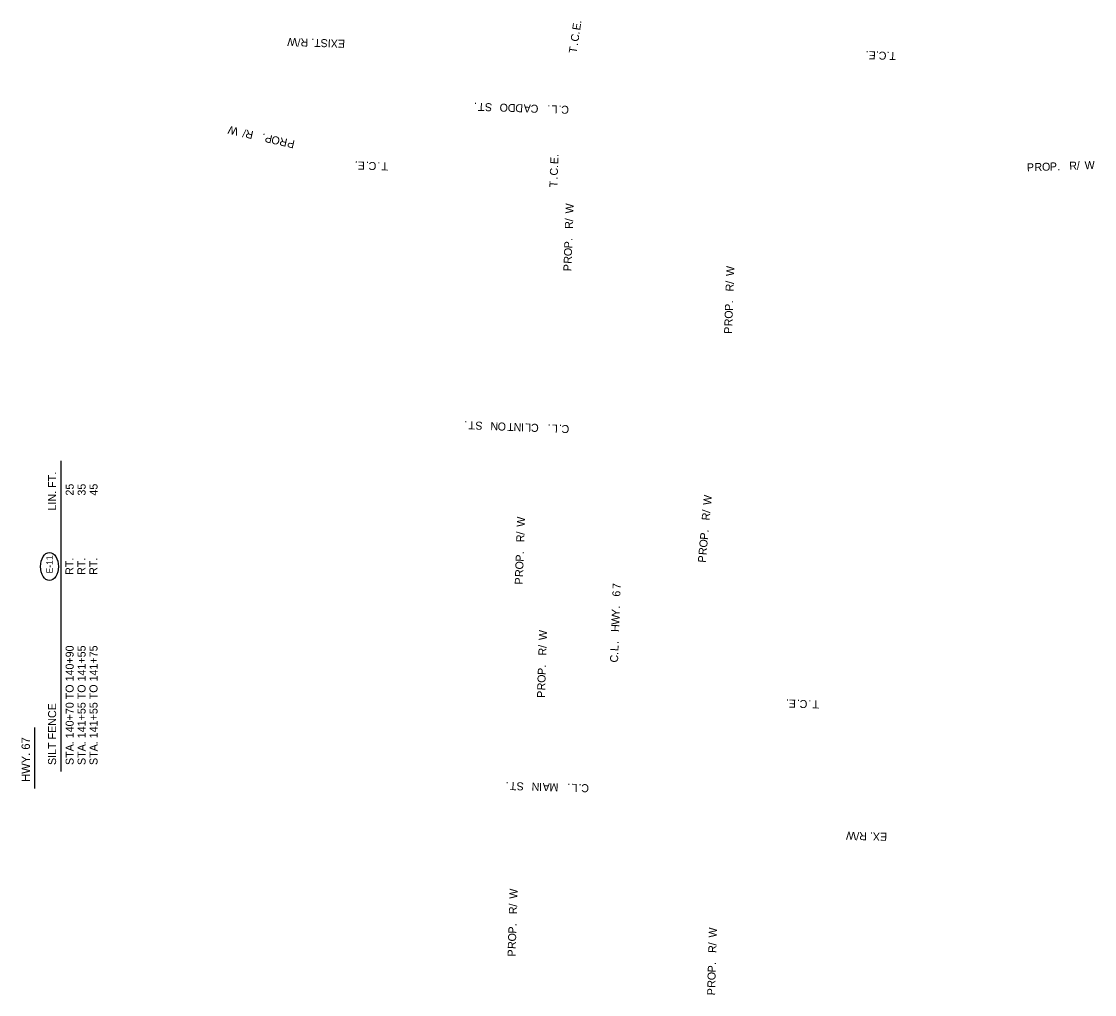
# Model space of a CAD drawing. Extents: x 992013 to 993002, y 1842718 to 1844294.
# Drawn here: x 992032 to 992837, y 1842718 to 1843448 of the extents above; entities that cross this region are included whole.
import ezdxf

# ---------------------------------------------------------------- set-up
doc = ezdxf.new("R2010")
doc.units = 0
for name, color, linetype in [('1', 7, 'Continuous'), ('44', 7, 'Continuous'), ('R_Draft', 7, 'Continuous')]:
    doc.layers.add(name, color=color, linetype=linetype)

msp = doc.modelspace()

# ---------------------------------------------------------------- linework, layer by layer
at = {"layer": '1'}
msp.add_ellipse((992053.34, 1843039.27), major_axis=(0, 10.52), ratio=0.638788, dxfattribs=at)
at = {"layer": '44'}
for p, q in [((992062.06, 1842885.64), (992062.06, 1843118.44)), ((992042.46, 1842872.95), (992042.46, 1842918.53))]:
    msp.add_line(p, q, dxfattribs=at)

# ---------------------------------------------------------------- texts
at = {"layer": '1'}
msp.add_text('E-11', height=4.8, rotation=89.99998, dxfattribs=at).set_placement((992055.7, 1843034.07))
at = {"layer": '44'}
for s, height, rotation, p in [('LIN. FT.', 6, 89.99998, (992058.3, 1843081.29)), ('25', 6, 89.99998, (992071.48, 1843092.44)), ('35', 6, 89.99998, (992080.43, 1843092.44)), ('45', 6, 89.99998, (992089.38, 1843092.44)), ('RT.', 6, 89.99998, (992071.32, 1843033)), ('RT.', 6, 89.99998, (992080.26, 1843033)), ('RT.', 6, 89.99998, (992089.21, 1843033)), ('STA. 140+70 TO 140+90', 6, 89.99998, (992071.46, 1842890.43)), ('STA. 141+55 TO 141+55', 6, 89.99998, (992080.41, 1842890.43)), ('STA. 141+55 TO 141+75', 6, 89.99998, (992089.36, 1842890.43)), ('SILT FENCE      ', 6, 89.99998, (992058.3, 1842890.43)), ('HWY. 67', 6.25, 90, (992038.68, 1842877.8))]:
    msp.add_text(s, height=height, rotation=rotation, dxfattribs=at).set_placement(p)
at = {"layer": 'R_Draft'}
for s, rotation, p in [('E', 81.56837, (992451.09, 1843441)), ('.', 81.56837, (992451.88, 1843446.33)), ('C', 81.56837, (992449.83, 1843432.49)), ('.', 81.56837, (992450.66, 1843438.1)), ('EXIST. R/W', 178.05625, (992275, 1843434.16)), ('.', 81.56837, (992449.4, 1843429.6)), ('T', 81.56837, (992448.54, 1843423.8)), ('T.C.E.', 178.03611, (992688.02, 1843424.97)), ('.', 178.11944, (992373.75, 1843386.94)), ('T', 178.11944, (992379.6, 1843386.75)), ('S', 178.11944, (992385.27, 1843386.57)), ('O', 178.11944, (992397.12, 1843386.18)), ('D', 178.11944, (992402.79, 1843385.99)), ('D', 178.11944, (992408.45, 1843385.8)), ('A', 178.11944, (992414.31, 1843385.61)), ('C', 178.11944, (992419.98, 1843385.43)), ('.', 178.11944, (992428.9, 1843385.13)), ('L', 178.11944, (992434.28, 1843384.96)), ('.', 178.11944, (992437.21, 1843384.86)), ('C', 178.11944, (992442.88, 1843384.67)), ('W', 167.24084, (992195.38, 1843368.1)), ('/', 167.24084, (992201.09, 1843366.81)), ('R', 167.24084, (992206.62, 1843365.56)), ('.', 167.24084, (992215.33, 1843363.59)), ('P', 167.24084, (992220.86, 1843362.33)), ('O', 167.24084, (992226.57, 1843361.04)), ('R', 167.24084, (992232.1, 1843359.79)), ('P', 167.24084, (992237.63, 1843358.54)), ('.', 178.03179, (992284.51, 1843342.95)), ('E', 178.03179, (992289.89, 1843342.77)), ('.', 178.03179, (992292.82, 1843342.67)), ('C', 178.03179, (992298.48, 1843342.47)), ('.', 178.03179, (992301.41, 1843342.37)), ('T', 178.03179, (992307.27, 1843342.17)), ('E', 88.03611, (992434.7, 1843340.91)), ('.', 88.03611, (992434.89, 1843346.29)), ('P', 2.12172, (992786.17, 1843335.5)), ('R', 2.12172, (992791.84, 1843335.71)), ('O', 2.12172, (992797.5, 1843335.92)), ('P', 2.12172, (992803.36, 1843336.14)), ('R', 2.12172, (992817.95, 1843336.68)), ('/', 2.12172, (992823.61, 1843336.89)), ('W', 2.12172, (992829.47, 1843337.11)), ('C', 88.03611, (992434.41, 1843332.31)), ('.', 88.03611, (992434.6, 1843337.98)), ('.', 2.12172, (992809.02, 1843336.35)), ('T', 88.03611, (992434.11, 1843323.53)), ('.', 88.03611, (992434.31, 1843329.39)), ('W', 88.03611, (992446.06, 1843303.84)), ('/', 88.03611, (992445.86, 1843297.98)), ('R', 88.03611, (992445.66, 1843292.32)), ('O', 88.03611, (992444.96, 1843271.87)), ('P', 88.03611, (992445.16, 1843277.73)), ('.', 88.03611, (992445.36, 1843283.39)), ('R', 88.03611, (992444.77, 1843266.21)), ('P', 88.03611, (992444.57, 1843260.54)), ('W', 88.03611, (992566.52, 1843256.93)), ('/', 88.03611, (992566.32, 1843251.08)), ('R', 88.03611, (992566.12, 1843245.41)), ('.', 88.03611, (992565.82, 1843236.49)), ('O', 88.03611, (992565.42, 1843224.97)), ('P', 88.03611, (992565.62, 1843230.82)), ('R', 88.03611, (992565.23, 1843219.3)), ('P', 88.03611, (992565.04, 1843213.63)), ('.', 177.78611, (992366.65, 1843148.21)), ('T', 177.78611, (992372.51, 1843147.98)), ('S', 177.78611, (992378.17, 1843147.76)), ('N', 177.78611, (992389.83, 1843147.31)), ('O', 177.78611, (992395.69, 1843147.09)), ('T', 177.78611, (992401.54, 1843146.86)), ('N', 177.78611, (992407.21, 1843146.64)), ('I', 177.78611, (992409.19, 1843146.57)), ('L', 177.78611, (992414.57, 1843146.36)), ('C', 177.78611, (992420.24, 1843146.14)), ('.', 177.78611, (992429.16, 1843145.79)), ('L', 177.78611, (992434.54, 1843145.59)), ('.', 177.78611, (992437.47, 1843145.47)), ('C', 177.78611, (992443.13, 1843145.25)), ('W', 84.78093, (992549.24, 1843085.1)), ('W', 88.03611, (992409.62, 1843068.92)), ('R', 84.78093, (992548.19, 1843073.62)), ('/', 84.78093, (992548.71, 1843079.26)), ('/', 88.03611, (992409.42, 1843063.07)), ('R', 88.03611, (992409.22, 1843057.4)), ('P', 84.78093, (992546.86, 1843059.08)), ('.', 84.78093, (992547.38, 1843064.72)), ('R', 84.78093, (992545.81, 1843047.6)), ('O', 84.78093, (992546.33, 1843053.24)), ('P', 88.03611, (992408.72, 1843042.81)), ('.', 88.03611, (992408.92, 1843048.48)), ('P', 84.78093, (992545.3, 1843041.95)), ('R', 88.03611, (992408.33, 1843031.29)), ('O', 88.03611, (992408.52, 1843036.95)), ('P', 88.03611, (992408.13, 1843025.62)), ('6', 88.03611, (992481.23, 1843016.59)), ('7', 88.03611, (992481.43, 1843022.26)), ('Y', 88.03611, (992480.73, 1843001.91)), ('.', 88.03611, (992480.93, 1843007.67)), ('W', 88.03611, (992480.51, 1842995.49)), ('W', 88.21353, (992426.13, 1842983.96)), ('H', 88.03611, (992480.33, 1842990.11)), ('/', 88.21353, (992425.94, 1842978.11)), ('L', 88.03611, (992479.83, 1842975.8)), ('.', 88.03611, (992480.02, 1842981.18)), ('R', 88.21353, (992425.77, 1842972.44)), ('C', 88.03611, (992479.54, 1842967.21)), ('.', 88.03611, (992479.73, 1842972.87)), ('.', 88.21353, (992425.49, 1842963.52)), ('O', 88.21353, (992425.13, 1842951.99)), ('P', 88.21353, (992425.31, 1842957.85)), ('R', 88.21353, (992424.95, 1842946.33)), ('P', 88.21353, (992424.77, 1842940.66)), ('.', 178.03611, (992607.66, 1842939.56)), ('E', 178.03611, (992613.04, 1842939.38)), ('.', 178.03611, (992615.97, 1842939.28)), ('C', 178.03611, (992621.63, 1842939.08)), ('.', 178.03611, (992624.56, 1842938.98)), ('T', 178.03611, (992630.42, 1842938.78)), ('.', 178.36944, (992397.51, 1842877.7)), ('T', 178.36944, (992403.36, 1842877.53)), ('S', 178.36944, (992409.03, 1842877.37)), ('N', 178.36944, (992420.69, 1842877.04)), ('I', 178.36944, (992422.68, 1842876.98)), ('A', 178.36944, (992428.53, 1842876.81)), ('M', 178.36944, (992434.95, 1842876.63)), ('.', 178.36944, (992443.88, 1842876.38)), ('L', 178.36944, (992449.26, 1842876.22)), ('.', 178.36944, (992452.19, 1842876.14)), ('C', 178.36944, (992457.86, 1842875.98)), ('EX. R/W', 178.36308, (992681.36, 1842839.57)), ('W', 88.21354, (992404.07, 1842790.04)), ('/', 88.21354, (992403.89, 1842784.18)), ('R', 88.21354, (992403.71, 1842778.52)), ('.', 88.21354, (992403.43, 1842769.59)), ('O', 88.21354, (992403.07, 1842758.07)), ('P', 88.21354, (992403.25, 1842763.93)), ('W', 88.24374, (992553.49, 1842760.95)), ('R', 88.21354, (992402.9, 1842752.4)), ('/', 88.30308, (992553.32, 1842755.1)), ('R', 88.3605, (992553.16, 1842749.43)), ('P', 88.21354, (992402.72, 1842746.74)), ('P', 88.50837, (992552.77, 1842734.86)), ('.', 88.45094, (992552.92, 1842740.52)), ('O', 88.56771, (992552.62, 1842729.01)), ('P', 88.68256, (992552.36, 1842717.68)), ('R', 88.62513, (992552.49, 1842723.35))]:
    msp.add_text(s, height=6, rotation=rotation, dxfattribs=at).set_placement(p)

doc.saveas('drawing.dxf')
